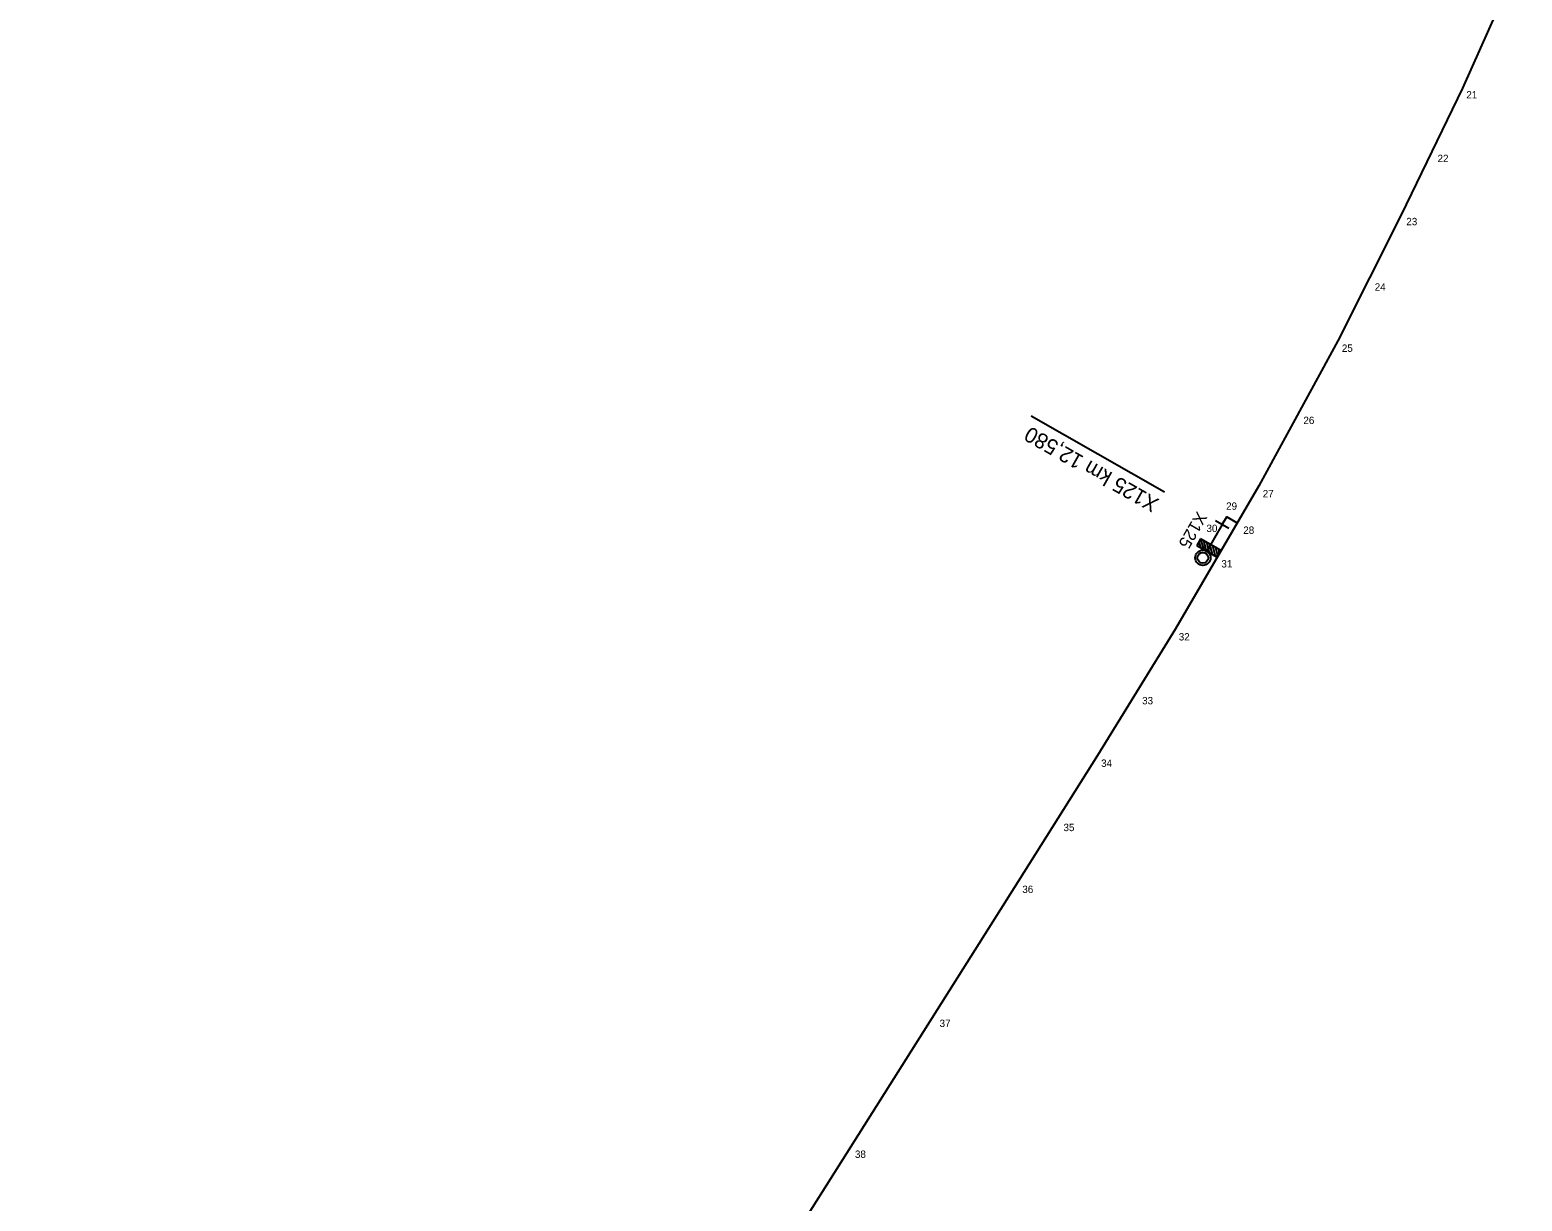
# Model space of a CAD drawing. Extents: x -743397 to -742769, y -1127804 to -1126284.
# Drawn here: x -743152.6 to -742909.3, y -1126856.5 to -1126665.7 of the extents above; entities that cross this region are included whole.
import ezdxf

# ---------------------------------------------------------------- set-up
doc = ezdxf.new("R2010")
doc.units = 0
for name, color, linetype in [('_Zabezpečovací zařízení', 7, 'Continuous'), ('_Zabezpečovací zařízení_trasa', 7, 'Continuous'), ('křížky', 7, 'Continuous'), ('Nový stav', 7, 'Continuous'), ('Vrstva 60', 7, 'Continuous')]:
    doc.layers.add(name, color=color, linetype=linetype)

# ---------------------------------------------------------------- blocks, each defined once
blk = doc.blocks.new('POINT_DISPLAY')
blk.add_line((0, 0), (0, 0))

msp = doc.modelspace()

# ---------------------------------------------------------------- linework, layer by layer
at = {"layer": '_Zabezpečovací zařízení'}
for p, q in [((-742958.23, -1126746.33), (-742960.75, -1126750.66)), ((-742957.15, -1126746.96), (-742959.31, -1126745.71)), ((-742961.74, -1126748.63), (-742962.37, -1126749.71)), ((-742961.75, -1126748.64), (-742961.3, -1126750.34)), ((-742958.5, -1126750.52), (-742961.74, -1126748.63)), ((-742961.27, -1126748.91), (-742960.82, -1126750.62)), ((-742962.37, -1126749.71), (-742959.13, -1126751.6)), ((-742962.31, -1126749.61), (-742962.27, -1126749.77)), ((-742962.03, -1126749.13), (-742961.79, -1126750.05)), ((-742960.78, -1126749.19), (-742960.51, -1126750.24)), ((-742960.51, -1126750.24), (-742960.33, -1126750.9)), ((-742960.3, -1126749.47), (-742960.22, -1126749.75)), ((-742960.22, -1126749.75), (-742959.85, -1126751.18)), ((-742959.81, -1126749.76), (-742959.36, -1126751.46)), ((-742959.33, -1126750.04), (-742958.98, -1126751.35)), ((-742959.13, -1126751.6), (-742958.5, -1126750.52)), ((-742958.84, -1126750.32), (-742958.7, -1126750.86))]:
    msp.add_line(p, q, dxfattribs=at)
for radius in [1.25, 0.875]:
    msp.add_circle((-742961.38, -1126751.74), radius, dxfattribs=at)
at = {"layer": '_Zabezpečovací zařízení_trasa'}
for points in [[(-742909.33, -1126653.4), (-742919.08, -1126675.22), (-742929.03, -1126695.89), (-742939.4, -1126716.38), (-742952.25, -1126740.02), (-742965.82, -1126763.29), (-742978.53, -1126783.97), (-742991.5, -1126804.49), (-743018.82, -1126847.74), (-743049.28, -1126895.95), (-743072.49, -1126932.75), (-743098.65, -1126974.15), (-743125.94, -1127017.38), (-743152.6, -1127059.61)], [(-742958.23, -1126746.33), (-742957.49, -1126745.05), (-742955.77, -1126746.05)]]:
    msp.add_lwpolyline(points, dxfattribs=at)
at = {"layer": 'Nový stav'}
msp.add_line((-742967.65, -1126741.03), (-742989.39, -1126728.68), dxfattribs=at)
msp.add_line((-742967.65, -1126741.03), (-742989.39, -1126728.68), dxfattribs=at)
at = {"layer": 'Vrstva 60'}
for p, q in [((-742919.08, -1126675.22), (-742919.08, -1126675.22)), ((-742924.06, -1126685.55), (-742924.06, -1126685.55)), ((-742929.03, -1126695.89), (-742929.03, -1126695.89)), ((-742934.21, -1126706.13), (-742934.21, -1126706.13)), ((-742939.4, -1126716.38), (-742939.4, -1126716.38)), ((-742945.82, -1126728.2), (-742945.82, -1126728.2)), ((-742952.25, -1126740.02), (-742952.25, -1126740.02)), ((-742958.23, -1126746.33), (-742958.23, -1126746.33)), ((-742957.49, -1126745.05), (-742957.49, -1126745.05)), ((-742955.77, -1126746.05), (-742955.77, -1126746.05)), ((-742959.04, -1126751.66), (-742959.04, -1126751.66)), ((-742965.83, -1126763.29), (-742965.83, -1126763.29)), ((-742972.18, -1126773.63), (-742972.18, -1126773.63)), ((-742978.53, -1126783.97), (-742978.53, -1126783.97)), ((-742985.02, -1126794.23), (-742985.02, -1126794.23)), ((-742991.51, -1126804.49), (-742991.51, -1126804.49)), ((-743005.16, -1126826.11), (-743005.16, -1126826.11)), ((-743018.82, -1126847.74), (-743018.82, -1126847.74))]:
    msp.add_line(p, q, dxfattribs=at)

# ---------------------------------------------------------------- block references
at = {"layer": 'křížky', "xscale": 10, "yscale": 10, "rotation": 61.14491455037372}
for p in [(-742919.08, -1126675.22), (-742924.06, -1126685.55), (-742929.03, -1126695.89), (-742934.21, -1126706.13), (-742939.4, -1126716.38), (-742945.82, -1126728.2), (-742952.25, -1126740.02), (-742958.23, -1126746.33), (-742957.49, -1126745.05), (-742955.77, -1126746.05), (-742959.04, -1126751.66), (-742965.83, -1126763.29), (-742972.18, -1126773.63), (-742978.53, -1126783.97), (-742985.02, -1126794.23), (-742991.51, -1126804.49), (-743005.16, -1126826.11), (-743018.82, -1126847.74)]:
    msp.add_blockref('POINT_DISPLAY', p, dxfattribs=at)

# ---------------------------------------------------------------- texts
at = {"layer": '_Zabezpečovací zařízení'}
msp.add_text('X125', height=2, rotation=239.923, dxfattribs=at).set_placement((-742962.3, -1126744.05))
at = {"layer": 'Nový stav'}
msp.add_text('X125 km 12,580', height=2.5, rotation=150.395, dxfattribs=at).set_placement((-742968.36, -1126742.27))
msp.add_text('X125 km 12,580', height=2.5, rotation=150.395, dxfattribs=at).set_placement((-742968.36, -1126742.27))
at = {"layer": 'Vrstva 60'}
for s, p in [('21', (-742918.43, -1126676.91)), ('22', (-742923.12, -1126687.28)), ('23', (-742928.21, -1126697.56)), ('24', (-742933.36, -1126708.22)), ('25', (-742938.72, -1126718.19)), ('26', (-742944.99, -1126729.95)), ('27', (-742951.62, -1126741.89)), ('29', (-742957.59, -1126743.92)), ('30', (-742960.79, -1126747.54)), ('28', (-742954.79, -1126747.84)), ('31', (-742958.36, -1126753.32)), ('32', (-742965.31, -1126765.21)), ('33', (-742971.28, -1126775.61)), ('34', (-742977.97, -1126785.8)), ('35', (-742984.1, -1126796.27)), ('36', (-742990.81, -1126806.35)), ('37', (-743004.3, -1126828.18)), ('38', (-743018.1, -1126849.5))]:
    msp.add_text(s, height=1.2, dxfattribs=at).set_placement(p)

doc.saveas('drawing.dxf')
